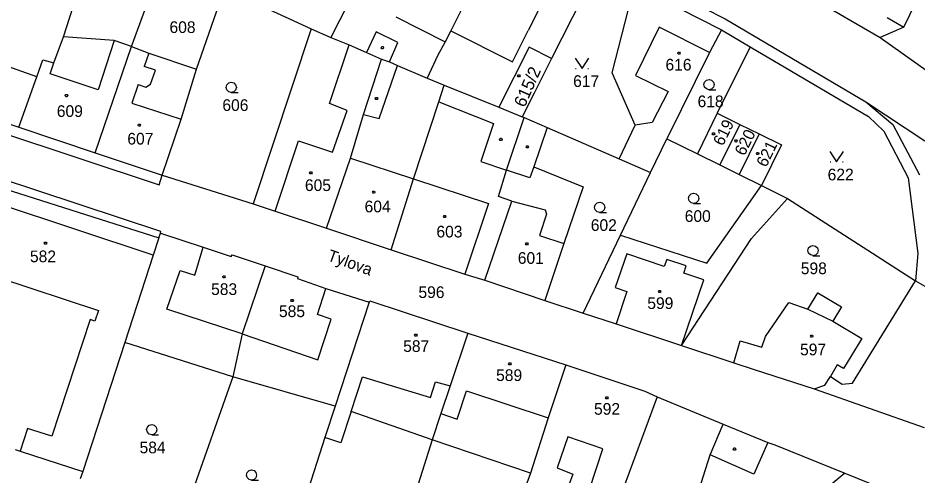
# Model space of a CAD drawing. Extents: x -621797 to -620972, y -1175539 to -1174697.
# Drawn here: x -621614.9 to -621483.9, y -1174979.5 to -1174912.8 of the extents above; entities that cross this region are included whole.
import ezdxf

# ---------------------------------------------------------------- set-up
doc = ezdxf.new("R2010")
doc.units = 0
for name, color, linetype in [('INZ mimo EON - nadz', 7, 'Continuous'), ('Rozvod plynu EON', 7, 'Continuous'), ('SDEL EON', 7, 'Continuous'), ('SDEL EON - popis', 7, 'Continuous'), ('Silnoproud EON', 7, 'Continuous'), ('Silnoproud EON - popis', 7, 'Continuous')]:
    doc.layers.add(name, color=color, linetype=linetype)

msp = doc.modelspace()

# ---------------------------------------------------------------- linework, layer by layer
at = {"layer": 'Rozvod plynu EON'}
for points in [[(-621561.79, -1174917.01), (-621561.7, -1174917.16), (-621561.79, -1174917.31), (-621561.97, -1174917.31), (-621562.06, -1174917.16), (-621561.97, -1174917.01)], [(-621518.61, -1174917.79), (-621518.52, -1174917.94), (-621518.61, -1174918.09), (-621518.79, -1174918.09), (-621518.88, -1174917.94), (-621518.79, -1174917.79)], [(-621541.93, -1174921.12), (-621541.84, -1174921.27), (-621541.93, -1174921.42), (-621542.11, -1174921.42), (-621542.2, -1174921.27), (-621542.11, -1174921.12)], [(-621607.79, -1174923.99), (-621607.7, -1174924.14), (-621607.79, -1174924.29), (-621607.97, -1174924.29), (-621608.06, -1174924.14), (-621607.97, -1174923.99)], [(-621562.65, -1174924.39), (-621562.56, -1174924.54), (-621562.65, -1174924.69), (-621562.83, -1174924.69), (-621562.92, -1174924.54), (-621562.83, -1174924.39)], [(-621597.2, -1174928.3), (-621597.11, -1174928.45), (-621597.2, -1174928.6), (-621597.38, -1174928.6), (-621597.47, -1174928.45), (-621597.38, -1174928.3)], [(-621544.55, -1174930.35), (-621544.46, -1174930.5), (-621544.55, -1174930.65), (-621544.73, -1174930.65), (-621544.82, -1174930.5), (-621544.73, -1174930.35)], [(-621513.57, -1174929.54), (-621513.48, -1174929.69), (-621513.57, -1174929.84), (-621513.75, -1174929.84), (-621513.84, -1174929.69), (-621513.75, -1174929.54)], [(-621510.3, -1174930.59), (-621510.21, -1174930.74), (-621510.3, -1174930.89), (-621510.48, -1174930.89), (-621510.57, -1174930.74), (-621510.48, -1174930.59)], [(-621540.69, -1174931.43), (-621540.6, -1174931.58), (-621540.69, -1174931.73), (-621540.87, -1174931.73), (-621540.96, -1174931.58), (-621540.87, -1174931.43)], [(-621507.13, -1174932.39), (-621507.04, -1174932.54), (-621507.13, -1174932.69), (-621507.31, -1174932.69), (-621507.4, -1174932.54), (-621507.31, -1174932.39)], [(-621572.21, -1174935.21), (-621572.12, -1174935.36), (-621572.21, -1174935.51), (-621572.39, -1174935.51), (-621572.48, -1174935.36), (-621572.39, -1174935.21)], [(-621563.05, -1174938.02), (-621562.96, -1174938.17), (-621563.05, -1174938.32), (-621563.23, -1174938.32), (-621563.32, -1174938.17), (-621563.23, -1174938.02)], [(-621552.72, -1174941.56), (-621552.63, -1174941.71), (-621552.72, -1174941.86), (-621552.9, -1174941.86), (-621552.99, -1174941.71), (-621552.9, -1174941.56)], [(-621610.86, -1174945.44), (-621610.77, -1174945.59), (-621610.86, -1174945.74), (-621611.04, -1174945.74), (-621611.13, -1174945.59), (-621611.04, -1174945.44)], [(-621540.76, -1174945.55), (-621540.67, -1174945.7), (-621540.76, -1174945.85), (-621540.94, -1174945.85), (-621541.03, -1174945.7), (-621540.94, -1174945.55)], [(-621584.87, -1174950.37), (-621584.78, -1174950.52), (-621584.87, -1174950.67), (-621585.05, -1174950.67), (-621585.14, -1174950.52), (-621585.05, -1174950.37)], [(-621521.41, -1174952.49), (-621521.32, -1174952.64), (-621521.41, -1174952.79), (-621521.59, -1174952.79), (-621521.68, -1174952.64), (-621521.59, -1174952.49)], [(-621574.93, -1174953.82), (-621574.84, -1174953.97), (-621574.93, -1174954.12), (-621575.11, -1174954.12), (-621575.2, -1174953.97), (-621575.11, -1174953.82)], [(-621556.93, -1174958.85), (-621556.84, -1174959), (-621556.93, -1174959.15), (-621557.11, -1174959.15), (-621557.2, -1174959), (-621557.11, -1174958.85)], [(-621499.27, -1174958.98), (-621499.18, -1174959.13), (-621499.27, -1174959.28), (-621499.45, -1174959.28), (-621499.54, -1174959.13), (-621499.45, -1174958.98)], [(-621543.23, -1174963.03), (-621543.14, -1174963.18), (-621543.23, -1174963.33), (-621543.41, -1174963.33), (-621543.5, -1174963.18), (-621543.41, -1174963.03)], [(-621529.1, -1174967.95), (-621529.01, -1174968.1), (-621529.1, -1174968.25), (-621529.28, -1174968.25), (-621529.37, -1174968.1), (-621529.28, -1174967.95)], [(-621510.52, -1174975.42), (-621510.43, -1174975.57), (-621510.52, -1174975.72), (-621510.7, -1174975.72), (-621510.79, -1174975.57), (-621510.7, -1174975.42)]]:
    msp.add_lwpolyline(points, close=True, dxfattribs=at)
at = {"layer": 'SDEL EON'}
for p, q in [((-621533.75, -1174920.17), (-621533.65, -1174920.17)), ((-621531.95, -1174920.17), (-621531.85, -1174920.17)), ((-621496.69, -1174933.77), (-621496.59, -1174933.77)), ((-621494.89, -1174933.77), (-621494.79, -1174933.77))]:
    msp.add_line(p, q, dxfattribs=at)
for points in [[(-621533.8, -1174918.67), (-621532.8, -1174920.17), (-621531.8, -1174918.67)], [(-621583.88, -1174923.67), (-621584.26, -1174923.57), (-621584.53, -1174923.3), (-621584.63, -1174922.93), (-621584.53, -1174922.56), (-621584.26, -1174922.29), (-621583.89, -1174922.19), (-621583.52, -1174922.29), (-621583.25, -1174922.56), (-621583.15, -1174922.94), (-621583.25, -1174923.32), (-621583.52, -1174923.59), (-621583.9, -1174923.69), (-621582.9, -1174923.69)], [(-621514.31, -1174923.27), (-621514.69, -1174923.17), (-621514.96, -1174922.9), (-621515.06, -1174922.53), (-621514.96, -1174922.16), (-621514.69, -1174921.89), (-621514.32, -1174921.79), (-621513.95, -1174921.89), (-621513.68, -1174922.16), (-621513.58, -1174922.54), (-621513.68, -1174922.92), (-621513.95, -1174923.19), (-621514.33, -1174923.29), (-621513.33, -1174923.29)], [(-621496.74, -1174932.27), (-621495.74, -1174933.77), (-621494.74, -1174932.27)], [(-621516.55, -1174939.82), (-621516.93, -1174939.72), (-621517.2, -1174939.45), (-621517.3, -1174939.08), (-621517.2, -1174938.71), (-621516.93, -1174938.44), (-621516.56, -1174938.34), (-621516.19, -1174938.44), (-621515.92, -1174938.71), (-621515.82, -1174939.09), (-621515.92, -1174939.47), (-621516.19, -1174939.74), (-621516.57, -1174939.84), (-621515.57, -1174939.84)], [(-621530.23, -1174941.13), (-621530.61, -1174941.03), (-621530.88, -1174940.76), (-621530.98, -1174940.39), (-621530.88, -1174940.02), (-621530.61, -1174939.75), (-621530.24, -1174939.65), (-621529.87, -1174939.75), (-621529.6, -1174940.02), (-621529.5, -1174940.4), (-621529.6, -1174940.78), (-621529.87, -1174941.05), (-621530.25, -1174941.15), (-621529.25, -1174941.15)], [(-621499.17, -1174947.42), (-621499.55, -1174947.32), (-621499.82, -1174947.05), (-621499.92, -1174946.68), (-621499.82, -1174946.31), (-621499.55, -1174946.04), (-621499.18, -1174945.94), (-621498.81, -1174946.04), (-621498.54, -1174946.31), (-621498.44, -1174946.69), (-621498.54, -1174947.07), (-621498.81, -1174947.34), (-621499.19, -1174947.44), (-621498.19, -1174947.44)], [(-621595.46, -1174973.49), (-621595.84, -1174973.39), (-621596.11, -1174973.12), (-621596.21, -1174972.75), (-621596.11, -1174972.38), (-621595.84, -1174972.11), (-621595.47, -1174972.01), (-621595.1, -1174972.11), (-621594.83, -1174972.38), (-621594.73, -1174972.76), (-621594.83, -1174973.14), (-621595.1, -1174973.41), (-621595.48, -1174973.51), (-621594.48, -1174973.51)], [(-621580.92, -1174980.1), (-621581.3, -1174980), (-621581.57, -1174979.73), (-621581.67, -1174979.36), (-621581.57, -1174978.99), (-621581.3, -1174978.72), (-621580.93, -1174978.62), (-621580.56, -1174978.72), (-621580.29, -1174978.99), (-621580.19, -1174979.37), (-621580.29, -1174979.75), (-621580.56, -1174980.02), (-621580.94, -1174980.12), (-621579.94, -1174980.12)]]:
    msp.add_lwpolyline(points, dxfattribs=at)
at = {"layer": 'SDEL EON - popis'}
for p, q in [((-621536.66, -1174906.74), (-621540.66, -1174914.68)), ((-621485.93, -1174914.19), (-621484.21, -1174910.57)), ((-621559.93, -1174912.69), (-621552.74, -1174916.32)), ((-621562.78, -1174914.85), (-621564.19, -1174917.85)), ((-621559.64, -1174916.42), (-621562.78, -1174914.85)), ((-621551.93, -1174914.7), (-621542.94, -1174919.2)), ((-621542.94, -1174919.2), (-621540.66, -1174914.68)), ((-621521.56, -1174914.15), (-621525.01, -1174921.21)), ((-621514.25, -1174917.86), (-621521.56, -1174914.15)), ((-621600.94, -1174916.1), (-621608.32, -1174915.56)), ((-621600.94, -1174916.1), (-621603.26, -1174923.3)), ((-621598.4, -1174917), (-621600.94, -1174916.1)), ((-621569.6, -1174925.28), (-621566.74, -1174916.76)), ((-621560.84, -1174919.2), (-621559.64, -1174916.42)), ((-621595.9, -1174917.94), (-621596.56, -1174919.9)), ((-621612.2, -1174921.39), (-621618.88, -1174919.05)), ((-621610.27, -1174920.95), (-621609.72, -1174919.36)), ((-621594.93, -1174920.44), (-621596.56, -1174919.9)), ((-621562.33, -1174927.45), (-621559.69, -1174919.74)), ((-621603.26, -1174923.3), (-621610.27, -1174920.95)), ((-621595.64, -1174922.49), (-621594.93, -1174920.44)), ((-621525.01, -1174921.21), (-621520.26, -1174923.53)), ((-621638.43, -1174922.48), (-621594.39, -1174937.13)), ((-621597.44, -1174922.54), (-621598.35, -1174925.24)), ((-621597.44, -1174922.54), (-621596.35, -1174922.9)), ((-621596.35, -1174922.9), (-621595.64, -1174922.49)), ((-621520.26, -1174923.53), (-621522.61, -1174928.05)), ((-621598.35, -1174925.24), (-621591.17, -1174927.54)), ((-621567.02, -1174926.32), (-621569.6, -1174925.28)), ((-621553.65, -1174925.02), (-621545.71, -1174928.2)), ((-621569.13, -1174932.37), (-621567.02, -1174926.32)), ((-621564.61, -1174926.89), (-621562.33, -1174927.45)), ((-621594.15, -1174943.9), (-621639.01, -1174929.15)), ((-621545.71, -1174928.2), (-621547.54, -1174933.71)), ((-621522.61, -1174928.05), (-621525.07, -1174928.43)), ((-621577.48, -1174940.94), (-621574.08, -1174930.73)), ((-621574.08, -1174930.73), (-621569.13, -1174932.37)), ((-621566.52, -1174933.23), (-621557.33, -1174936.27)), ((-621595.24, -1174947.37), (-621634.38, -1174934.4)), ((-621547.54, -1174933.71), (-621543.8, -1174934.99)), ((-621539.85, -1174934.5), (-621540.39, -1174936.11)), ((-621594.39, -1174937.13), (-621593.96, -1174935.7)), ((-621540.39, -1174936.11), (-621543.8, -1174934.99)), ((-621557.33, -1174936.27), (-621546.43, -1174939.84)), ((-621543.05, -1174939.52), (-621538.19, -1174940.78)), ((-621546.43, -1174939.84), (-621549.86, -1174950.1)), ((-621538.19, -1174940.78), (-621537.98, -1174941.39)), ((-621537.98, -1174941.39), (-621539.02, -1174944.47)), ((-621594.2, -1174944.16), (-621594.15, -1174943.9)), ((-621539.02, -1174944.47), (-621535.46, -1174945.67)), ((-621589.18, -1174950.27), (-621587.97, -1174946.2)), ((-621628.62, -1174947.05), (-621603.23, -1174955.42)), ((-621526.3, -1174947.15), (-621527.99, -1174952.08)), ((-621520.84, -1174949.02), (-621526.3, -1174947.15)), ((-621520.47, -1174947.97), (-621520.84, -1174949.02)), ((-621517.65, -1174948.91), (-621520.47, -1174947.97)), ((-621518, -1174949.99), (-621517.65, -1174948.91)), ((-621593.27, -1174955.23), (-621591.35, -1174949.6)), ((-621591.35, -1174949.6), (-621589.18, -1174950.27)), ((-621515.08, -1174950.96), (-621518, -1174949.99)), ((-621518.31, -1174960.52), (-621515.08, -1174950.96)), ((-621571.33, -1174955.99), (-621570.14, -1174952.21)), ((-621527.99, -1174952.08), (-621526.27, -1174952.66)), ((-621526.27, -1174952.66), (-621527.84, -1174957.35)), ((-621603.23, -1174955.42), (-621603.74, -1174956.98)), ((-621582.32, -1174958.81), (-621593.27, -1174955.23)), ((-621499.95, -1174955.2), (-621496.31, -1174956.97)), ((-621604.44, -1174956.7), (-621610.01, -1174973.72)), ((-621603.74, -1174956.98), (-621604.44, -1174956.7)), ((-621569.34, -1174956.68), (-621571.33, -1174955.99)), ((-621571.28, -1174962.57), (-621569.34, -1174956.68)), ((-621582.32, -1174958.81), (-621571.28, -1174962.57)), ((-621566.44, -1174970.09), (-621564.79, -1174965.06)), ((-621564.79, -1174965.06), (-621554.88, -1174968.05)), ((-621554.88, -1174968.05), (-621554.15, -1174965.8)), ((-621554.15, -1174965.8), (-621552.01, -1174966.38)), ((-621550.99, -1174971.24), (-621549.62, -1174967.09)), ((-621549.62, -1174967.09), (-621537.72, -1174971.02)), ((-621499.01, -1174966.83), (-621483.01, -1174972.44)), ((-621553.35, -1174970.41), (-621550.99, -1174971.24)), ((-621613.56, -1174972.57), (-621614.64, -1174975.9)), ((-621610.01, -1174973.72), (-621613.56, -1174972.57)), ((-621534.87, -1174973.79), (-621536.43, -1174978.32)), ((-621529.78, -1174975.54), (-621534.87, -1174973.79)), ((-621505.76, -1174974.64), (-621507.77, -1174979.24)), ((-621531.79, -1174981.59), (-621529.78, -1174975.54)), ((-621507.77, -1174979.24), (-621514.14, -1174976.41)), ((-621536.43, -1174978.32), (-621534.14, -1174979.21)), ((-621534.14, -1174979.21), (-621536.49, -1174985.57))]:
    msp.add_line(p, q, dxfattribs=at)
at = {"layer": 'Silnoproud EON'}
for p, q in [((-621558.17, -1174889.39), (-621511.97, -1174912.96)), ((-621545.7, -1174902.28), (-621551.93, -1174914.7)), ((-621509.01, -1174904.22), (-621489.4, -1174915.7)), ((-621598.4, -1174917), (-621594.11, -1174905.11)), ((-621530.48, -1174905.4), (-621537.24, -1174918.72)), ((-621608.32, -1174915.56), (-621605.65, -1174907.25)), ((-621528.4, -1174920.83), (-621525.16, -1174908.11)), ((-621525.16, -1174908.11), (-621512.52, -1174914.55)), ((-621588.97, -1174920.27), (-621584.88, -1174908.59)), ((-621584.88, -1174908.59), (-621575.51, -1174912.9)), ((-621566.85, -1174910.73), (-621569.41, -1174915.7)), ((-621575.51, -1174912.9), (-621572.24, -1174914.4)), ((-621511.97, -1174912.96), (-621491.48, -1174925.04)), ((-621488.38, -1174912.78), (-621485.93, -1174914.19)), ((-621572.24, -1174914.4), (-621580.71, -1174939.9)), ((-621572.24, -1174914.4), (-621569.41, -1174915.7)), ((-621551.93, -1174914.7), (-621552.74, -1174916.32)), ((-621512.52, -1174914.55), (-621514.25, -1174917.86)), ((-621512.52, -1174914.55), (-621508.31, -1174917.05)), ((-621485.93, -1174914.19), (-621489.4, -1174915.7)), ((-621609.72, -1174919.36), (-621608.32, -1174915.56)), ((-621569.41, -1174915.7), (-621566.74, -1174916.76)), ((-621489.4, -1174915.7), (-621474.63, -1174926.2)), ((-621603.72, -1174932.46), (-621598.4, -1174917)), ((-621598.4, -1174917), (-621595.9, -1174917.94)), ((-621566.74, -1174916.76), (-621564.19, -1174917.85)), ((-621552.74, -1174916.32), (-621553.88, -1174918.34)), ((-621540.51, -1174917.06), (-621544.94, -1174925.83)), ((-621537.24, -1174918.72), (-621540.51, -1174917.06)), ((-621508.31, -1174917.05), (-621513.13, -1174926.71)), ((-621508.31, -1174917.05), (-621491.07, -1174927.18)), ((-621595.9, -1174917.94), (-621588.97, -1174920.27)), ((-621564.61, -1174926.89), (-621561.99, -1174918.81)), ((-621564.19, -1174917.85), (-621561.99, -1174918.81)), ((-621561.99, -1174918.81), (-621560.84, -1174919.2)), ((-621553.88, -1174918.34), (-621555.34, -1174921.61)), ((-621537.24, -1174918.72), (-621539.8, -1174923.76)), ((-621514.25, -1174917.86), (-621520.44, -1174930.44)), ((-621612.2, -1174921.39), (-621611.32, -1174918.94)), ((-621611.32, -1174918.94), (-621609.72, -1174919.36)), ((-621560.84, -1174919.2), (-621559.69, -1174919.74)), ((-621559.69, -1174919.74), (-621555.34, -1174921.61)), ((-621638, -1174921.06), (-621614.82, -1174928.75)), ((-621614.82, -1174928.75), (-621612.2, -1174921.39)), ((-621591.17, -1174927.54), (-621588.97, -1174920.27)), ((-621525.07, -1174928.43), (-621528.4, -1174920.83)), ((-621555.34, -1174921.61), (-621552.88, -1174922.62)), ((-621553.65, -1174925.02), (-621552.88, -1174922.62)), ((-621552.88, -1174922.62), (-621544.94, -1174925.83)), ((-621539.8, -1174923.76), (-621541.55, -1174927.2)), ((-621557.33, -1174936.27), (-621553.65, -1174925.02)), ((-621491.48, -1174925.04), (-621487.55, -1174928.32)), ((-621491.48, -1174925.04), (-621482.89, -1174930.73)), ((-621544.94, -1174925.83), (-621541.55, -1174927.2)), ((-621593.96, -1174935.7), (-621591.17, -1174927.54)), ((-621566.52, -1174933.23), (-621564.61, -1174926.89)), ((-621543.8, -1174934.99), (-621541.22, -1174927.32)), ((-621541.55, -1174927.2), (-621541.22, -1174927.32)), ((-621541.22, -1174927.32), (-621537.91, -1174928.76)), ((-621513.13, -1174926.71), (-621516.01, -1174932.62)), ((-621513.13, -1174926.71), (-621509.84, -1174928.32)), ((-621491.07, -1174927.18), (-621488.88, -1174929.29)), ((-621614.82, -1174928.75), (-621603.72, -1174932.46)), ((-621537.91, -1174928.76), (-621539.85, -1174934.5)), ((-621537.91, -1174928.76), (-621527.38, -1174933.34)), ((-621527.38, -1174933.34), (-621525.07, -1174928.43)), ((-621509.84, -1174928.32), (-621512.73, -1174934.23)), ((-621509.84, -1174928.32), (-621507, -1174929.72)), ((-621488.88, -1174929.29), (-621485.34, -1174936.08)), ((-621487.55, -1174928.32), (-621483.68, -1174935.67)), ((-621522.86, -1174935.31), (-621520.44, -1174930.44)), ((-621520.44, -1174930.44), (-621516.01, -1174932.62)), ((-621507, -1174929.72), (-621509.91, -1174935.61)), ((-621507, -1174929.72), (-621503.74, -1174931.32)), ((-621639.11, -1174930.68), (-621594.45, -1174944.82)), ((-621503.74, -1174931.32), (-621506.66, -1174937.2)), ((-621603.72, -1174932.46), (-621593.96, -1174935.7)), ((-621570.01, -1174943.42), (-621566.52, -1174933.23)), ((-621516.01, -1174932.62), (-621512.73, -1174934.23)), ((-621539.85, -1174934.5), (-621532.62, -1174937.42)), ((-621527.38, -1174933.34), (-621522.86, -1174935.31)), ((-621512.73, -1174934.23), (-621509.91, -1174935.61)), ((-621593.96, -1174935.7), (-621580.71, -1174939.9)), ((-621544.99, -1174938.84), (-621543.8, -1174934.99)), ((-621527.21, -1174944.43), (-621522.86, -1174935.31)), ((-621509.91, -1174935.61), (-621506.66, -1174937.2)), ((-621560.58, -1174946.59), (-621557.33, -1174936.27)), ((-621485.34, -1174936.08), (-621483.92, -1174947.11)), ((-621532.62, -1174937.42), (-621535.46, -1174945.67)), ((-621514.64, -1174948.51), (-621506.66, -1174937.2)), ((-621506.66, -1174937.2), (-621502.89, -1174939.13)), ((-621546.98, -1174951.01), (-621543.05, -1174939.52)), ((-621543.05, -1174939.52), (-621544.99, -1174938.84)), ((-621508.15, -1174944.94), (-621502.89, -1174939.13)), ((-621502.89, -1174939.13), (-621484.23, -1174951.09)), ((-621580.71, -1174939.9), (-621580.42, -1174939.99)), ((-621580.42, -1174939.99), (-621577.48, -1174940.94)), ((-621577.48, -1174940.94), (-621570.01, -1174943.42)), ((-621570.01, -1174943.42), (-621560.58, -1174946.59)), ((-621594.45, -1174944.82), (-621595.24, -1174947.37)), ((-621594.45, -1174944.82), (-621594.2, -1174944.16)), ((-621594.2, -1174944.16), (-621587.97, -1174946.2)), ((-621532.62, -1174955.78), (-621527.21, -1174944.43)), ((-621527.21, -1174944.43), (-621514.64, -1174948.51)), ((-621518.31, -1174960.52), (-621508.15, -1174944.94)), ((-621587.97, -1174946.2), (-621583.92, -1174947.56)), ((-621535.46, -1174945.67), (-621538.21, -1174953.96)), ((-621595.24, -1174947.37), (-621599.39, -1174960.09)), ((-621583.92, -1174947.56), (-621583.78, -1174947.32)), ((-621583.78, -1174947.32), (-621578.97, -1174948.9)), ((-621560.58, -1174946.59), (-621549.86, -1174950.1)), ((-621483.92, -1174947.11), (-621484.23, -1174951.09)), ((-621578.97, -1174948.9), (-621582.32, -1174958.81)), ((-621578.97, -1174948.9), (-621574.2, -1174950.5)), ((-621549.86, -1174950.1), (-621546.98, -1174951.01)), ((-621574.2, -1174950.5), (-621574.24, -1174950.77)), ((-621574.24, -1174950.77), (-621570.14, -1174952.21)), ((-621546.98, -1174951.01), (-621538.21, -1174953.96)), ((-621493.4, -1174965.98), (-621484.23, -1174951.09)), ((-621484.23, -1174951.09), (-621482.87, -1174951.87)), ((-621570.14, -1174952.21), (-621563.83, -1174954.22)), ((-621499.95, -1174955.2), (-621498.48, -1174952.82)), ((-621498.48, -1174952.82), (-621495.01, -1174954.88)), ((-621563.83, -1174954.22), (-621563.72, -1174954)), ((-621563.72, -1174954), (-621549.46, -1174958.69)), ((-621538.21, -1174953.96), (-621532.62, -1174955.78)), ((-621563.83, -1174954.22), (-621568.76, -1174969.31)), ((-621506.11, -1174959.18), (-621502.71, -1174954.24)), ((-621502.71, -1174954.24), (-621499.95, -1174955.2)), ((-621495.01, -1174954.88), (-621496.31, -1174956.97)), ((-621532.62, -1174955.78), (-621527.84, -1174957.35)), ((-621527.84, -1174957.35), (-621518.31, -1174960.52)), ((-621496.31, -1174956.97), (-621492.04, -1174959.5)), ((-621582.32, -1174958.81), (-621583.68, -1174965.08)), ((-621549.46, -1174958.69), (-621552.01, -1174966.38)), ((-621549.46, -1174958.69), (-621535.16, -1174963.32)), ((-621506.62, -1174960.74), (-621506.11, -1174959.18)), ((-621599.39, -1174960.09), (-621605.5, -1174978.83)), ((-621583.68, -1174965.08), (-621599.39, -1174960.09)), ((-621518.31, -1174960.52), (-621510.7, -1174963.05)), ((-621510.7, -1174963.05), (-621509.77, -1174959.83)), ((-621509.77, -1174959.83), (-621506.62, -1174960.74)), ((-621492.04, -1174959.5), (-621494.74, -1174963.84)), ((-621535.16, -1174963.32), (-621537.72, -1174971.02)), ((-621535.16, -1174963.32), (-621523.64, -1174967.13)), ((-621510.7, -1174963.05), (-621507.72, -1174964.02)), ((-621495.67, -1174963.31), (-621496.65, -1174965.01)), ((-621494.74, -1174963.84), (-621495.67, -1174963.31)), ((-621507.72, -1174964.02), (-621499.01, -1174966.83)), ((-621583.68, -1174965.08), (-621591.92, -1174988.4)), ((-621568.76, -1174969.31), (-621583.68, -1174965.08)), ((-621497.46, -1174966.26), (-621496.65, -1174965.01)), ((-621496.65, -1174965.01), (-621494.95, -1174966.13)), ((-621494.95, -1174966.13), (-621493.4, -1174965.98)), ((-621552.01, -1174966.38), (-621553.35, -1174970.41)), ((-621523.64, -1174967.13), (-621521.85, -1174967.99)), ((-621499.01, -1174966.83), (-621497.46, -1174966.26)), ((-621521.85, -1174967.99), (-621528.03, -1174984.58)), ((-621521.85, -1174967.99), (-621512.28, -1174971.96)), ((-621568.76, -1174969.31), (-621570.25, -1174973.87)), ((-621566.44, -1174970.09), (-621567.94, -1174974.68)), ((-621554.62, -1174974.24), (-621566.44, -1174970.09)), ((-621553.35, -1174970.41), (-621554.62, -1174974.24)), ((-621537.72, -1174971.02), (-621540.33, -1174979.1)), ((-621514.14, -1174976.41), (-621512.28, -1174971.96)), ((-621512.28, -1174971.96), (-621505.76, -1174974.64)), ((-621570.25, -1174973.87), (-621577.67, -1174996.89)), ((-621567.94, -1174974.68), (-621570.25, -1174973.87)), ((-621554.62, -1174974.24), (-621558.9, -1174987.56)), ((-621540.33, -1174979.1), (-621554.62, -1174974.24)), ((-621505.76, -1174974.64), (-621504.72, -1174974.97)), ((-621504.72, -1174974.97), (-621494.53, -1174979.08)), ((-621615.36, -1174975.63), (-621614.64, -1174975.9)), ((-621614.64, -1174975.9), (-621605.5, -1174978.83)), ((-621517.97, -1174988.23), (-621514.14, -1174976.41)), ((-621605.5, -1174978.83), (-621605.91, -1174979.93)), ((-621540.33, -1174979.1), (-621543.58, -1174988.09)), ((-621494.53, -1174979.08), (-621504.91, -1174987.66)), ((-621494.53, -1174979.08), (-621480.81, -1174984.62))]:
    msp.add_line(p, q, dxfattribs=at)

# ---------------------------------------------------------------- texts
at = {"layer": 'INZ mimo EON - nadz'}
msp.add_text('Tylova', height=1.7, rotation=340.22234, dxfattribs=at).set_placement((-621570.014, -1174948.08))
at = {"layer": 'Silnoproud EON - popis'}
for s, p in [('608', (-621592.883, -1174915.02)), ('616', (-621520.653, -1174920.48)), ('617', (-621534.103, -1174922.87)), ('606', (-621585.183, -1174926.37)), ('618', (-621515.983, -1174925.82)), ('609', (-621609.293, -1174927.24)), ('607', (-621599.023, -1174931.26)), ('622', (-621497.043, -1174936.47)), ('605', (-621573.163, -1174938.02)), ('604', (-621564.473, -1174941.12)), ('600', (-621517.853, -1174942.52)), ('602', (-621531.533, -1174943.83)), ('603', (-621554.013, -1174944.78)), ('582', (-621613.203, -1174948.38)), ('601', (-621542.163, -1174948.62)), ('598', (-621500.953, -1174950.12)), ('583', (-621586.823, -1174953.15)), ('596', (-621556.633, -1174953.59)), ('599', (-621523.303, -1174955.19)), ('585', (-621576.943, -1174956.37)), ('587', (-621558.853, -1174961.44)), ('597', (-621501.063, -1174961.93)), ('589', (-621545.323, -1174965.67)), ('592', (-621531.063, -1174970.58)), ('584', (-621597.243, -1174976.19))]:
    msp.add_text(s, height=1.7, dxfattribs=at).set_placement(p)
for s, height, rotation, p in [('615/2', 1.8, 66.17663, (-621541.168, -1174925.959)), ('619', 1.7, 63.88479, (-621512.293, -1174931.569)), ('620', 1.7, 63.88479, (-621509.153, -1174933.009)), ('621', 1.7, 63.88479, (-621505.993, -1174934.669))]:
    msp.add_text(s, height=height, rotation=rotation, dxfattribs=at).set_placement(p)

doc.saveas('drawing.dxf')
